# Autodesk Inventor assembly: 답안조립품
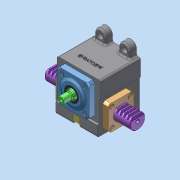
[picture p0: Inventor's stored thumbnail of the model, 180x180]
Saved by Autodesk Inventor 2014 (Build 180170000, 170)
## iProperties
Created: 2025-06
Part Number: 답안조립품
Document SubType Name: Assembly
Designer: dg
Author: dg
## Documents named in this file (10)
- C:\Users\dg\Desktop\650603V1010\답안조립품.iam
- C:\Users\dg\Desktop\650603V1010\가져온 구성요소\본체\본체.ipt
- C:\Users\dg\Desktop\650603V1010\가져온 구성요소\깊음 홈 볼 베어링 6202\깊음 홈 볼 베어링 6202.ipt
- C:\Users\dg\Desktop\650603V1010\가져온 구성요소\피니언 축\피니언 축.ipt
- C:\Users\dg\Desktop\650603V1010\가져온 구성요소\커버\커버.ipt
- C:\Users\dg\Desktop\650603V1010\가져온 구성요소\오일 실 15 25 4\오일 실 15 25 4.ipt
- C:\Users\dg\Desktop\650603V1010\가져온 구성요소\수지 부시\수지 부시.ipt
- C:\Users\dg\Desktop\650603V1010\가져온 구성요소\육각 소켓 머리 볼트 M4x10\육각 소켓 머리 볼트 M4x10.ipt
- C:\Users\dg\Desktop\650603V1010\가져온 구성요소\래크\래크.ipt
- C:\Users\dg\Desktop\650603V1010\가져온 구성요소\스톱퍼\스톱퍼.ipt
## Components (1 placed, 1 different names)
1. 피니언 축:1
